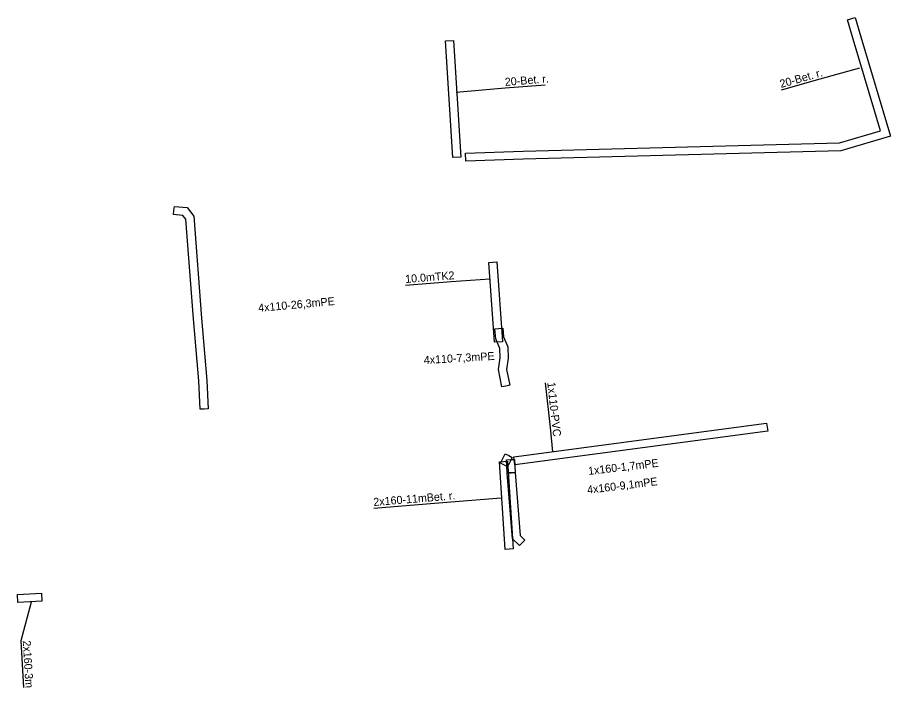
# Model space of a CAD drawing. Extents: x -744687 to -744578, y -1052418 to -1052334.
import ezdxf

# ---------------------------------------------------------------- set-up
doc = ezdxf.new("R2010")
doc.units = 0
doc.layers.add('Chránička', color=7, linetype='Continuous')
doc.layers.add('ST_CHRANICKA_POPIS', color=7, linetype='Continuous')

msp = doc.modelspace()

# ---------------------------------------------------------------- linework, layer by layer
at = {"layer": 'Chránička'}
for points in [[(-744631.159, -1052352.116), (-744631.195, -1052351.116), (-744624.017, -1052350.864), (-744584.511, -1052349.85), (-744579.373, -1052348.344), (-744582.787, -1052336.896), (-744583.508, -1052334.478), (-744582.55, -1052334.192), (-744581.829, -1052336.61), (-744578.127, -1052349.022), (-744584.355, -1052350.846), (-744623.987, -1052351.864), (-744631.159, -1052352.116)], [(-744631.794, -1052351.627), (-744632.792, -1052351.689), (-744633.69, -1052337.121), (-744632.692, -1052337.059), (-744631.794, -1052351.627)], [(-744664.36, -1052383.09), (-744664.5, -1052379.55), (-744665.18, -1052371.79), (-744666.13, -1052359.37), (-744666.49, -1052358.89), (-744667.66, -1052358.78), (-744667.61, -1052358.28), (-744667.56, -1052357.78), (-744665.97, -1052357.93), (-744665.15, -1052358.99), (-744664.18, -1052371.71), (-744663.5, -1052379.49), (-744663.36, -1052383.05), (-744663.86, -1052383.07), (-744664.36, -1052383.09)], [(-744626.591, -1052374.668), (-744627.589, -1052374.738), (-744628.287, -1052364.762), (-744627.289, -1052364.692), (-744626.591, -1052374.668)], [(-744626.66, -1052380.29), (-744627.09, -1052378.14), (-744626.88, -1052376.67), (-744626.9, -1052375.51), (-744627.43, -1052374.3), (-744627.53, -1052373.06), (-744627.03, -1052373.02), (-744626.53, -1052372.98), (-744626.45, -1052374.06), (-744625.9, -1052375.29), (-744625.88, -1052376.73), (-744626.07, -1052378.12), (-744625.68, -1052380.09), (-744626.17, -1052380.19), (-744626.66, -1052380.29)], [(-744625.19, -1052389.034), (-744593.597, -1052384.816), (-744593.464, -1052385.807), (-744625.057, -1052390.025), (-744625.19, -1052389.034)], [(-744625.36, -1052389.1), (-744625.95, -1052390.27), (-744626.4, -1052390.04), (-744626.85, -1052389.81), (-744626.26, -1052388.64), (-744625.81, -1052388.87), (-744625.36, -1052389.1)], [(-744625.24, -1052400.513), (-744626.238, -1052400.577), (-744626.949, -1052389.644), (-744625.951, -1052389.58), (-744625.24, -1052400.513)], [(-744626.02, -1052391.04), (-744626.07, -1052389.39), (-744625.57, -1052389.37), (-744625.07, -1052389.35), (-744625.02, -1052391), (-744625.52, -1052391.02), (-744626.02, -1052391.04)], [(-744624.48, -1052400.11), (-744625.32, -1052399.27), (-744626.02, -1052391.06), (-744625.52, -1052391.02), (-744625.02, -1052390.98), (-744624.36, -1052398.83), (-744623.78, -1052399.41), (-744624.13, -1052399.76), (-744624.48, -1052400.11)], [(-744687.108, -1052407.19), (-744687.158, -1052406.192), (-744684.162, -1052406.043), (-744684.112, -1052407.041), (-744687.108, -1052407.19)]]:
    msp.add_lwpolyline(points, close=True, dxfattribs=at)
at = {"layer": 'ST_CHRANICKA_POPIS'}
for points in [[(-744591.734, -1052343.236), (-744586.914, -1052341.87), (-744581.944, -1052340.498)], [(-744632.366, -1052343.501), (-744626.241, -1052342.99), (-744621.246, -1052342.601)], [(-744638.682, -1052367.589), (-744633.003, -1052367.144), (-744628.158, -1052366.8)], [(-744621.248, -1052379.781), (-744620.63, -1052385.375), (-744620.33, -1052388.405)], [(-744642.652, -1052395.422), (-744633.03, -1052394.635), (-744626.759, -1052394.157)], [(-744685.441, -1052407.157), (-744686.747, -1052411.989), (-744686.403, -1052417.812)]]:
    msp.add_lwpolyline(points, dxfattribs=at)

# ---------------------------------------------------------------- texts
for s, rotation, p in [('20-Bet. r.', 15.81766, (-744591.803, -1052342.995)), ('20-Bet. r.', 4.45188, (-744626.26, -1052342.74)), ('10.0mTK2', 4.47283, (-744638.701, -1052367.339)), ('4x110-26,3mPE', 5.19919, (-744657.05, -1052370.946)), ('4x110-7,3mPE', 3.39078, (-744636.386, -1052377.451)), ('1x110-PVC', 276.30231, (-744620.999, -1052379.754)), ('1x160-1,7mPE', 6.67909, (-744615.833, -1052391.292)), ('4x160-9,1mPE', 7.09623, (-744615.957, -1052393.655)), ('2x160-11mBet. r.', 4.67332, (-744642.672, -1052395.172)), ('2x160-3m', 273.38802, (-744686.498, -1052411.974))]:
    msp.add_text(s, height=1, rotation=rotation, dxfattribs=at).set_placement(p)

doc.saveas('drawing.dxf')
